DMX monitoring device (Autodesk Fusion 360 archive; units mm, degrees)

design "DMX monitoring device" references "rubber foot", "3D File NC5MAH", "longLCD_ESP32", "longLCD", "post", "nac3mpxxa", "3-D NC5FAH", "5V2AACDC", "conect"
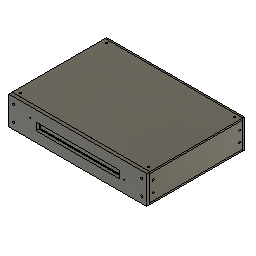
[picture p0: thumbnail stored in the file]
sketch "Sketch1" plane through (0, 0, 0) normal (0, 0, 1) x axis (1, 0, 0)
  line L1 (211.3, 0) -> (0, 0)
  line L2 (211.3, 150) -> (211.3, 0)
  line L3 (0, 150) -> (211.3, 150)
  line L4 (0, 0) -> (0, 150)
  point P1 (0, 0)
  point P2 (0, 0)
  point P3 (211.3, 0)
  point P5 (0, 150)
  horizontal L1
  vertical L2
  horizontal L3
  vertical L4
  coincident P1 P2
  dimension "d1" distance P2 P3 = 211.3
  dimension "d2" distance P2 P5 = 150
extrude "Extrude1" new body sketch "Sketch1" along normal blind 43.7
component_insert "Component Insert1"
component_insert "Component Insert2"
component_insert "Component Insert3"
component_insert "Component Insert4"
component_insert "Component Insert5"
component_insert "Component Insert6"
component_insert "Component Insert7"
component_insert "Component Insert8"
shell "Shell1" innerThickness 2.5
position "Position1" sketch "Sketch5"
sketch "Sketch2" plane through (0, 0, 0) normal (0, 0, 1) x axis (1, 0, 0)
  line L1 (211.3, 0) -> (0, 0)
  line L2 (211.3, 5) -> (211.3, 0)
  line L3 (0, 5) -> (211.3, 5)
  line L4 (0, 0) -> (0, 5)
  point P1 (0, 0)
  point P2 (0, 0)
  point P6 (211.3, 0)
  point P5 (0, 5)
  horizontal L1
  vertical L2
  horizontal L3
  vertical L4
  coincident P1 P2
  coincident L2 P6
  dimension "d6" distance P2 P5 = 5
extrude "Extrude1" new body sketch "Sketch2" to an object
sketch "Sketch4" plane through (0, 0, 0) normal (0, 0, 1) x axis (1, 0, 0)
  line L1 (211.3, 150) -> (0, 150)
  line L2 (211.3, 147.5) -> (211.3, 150)
  line L3 (0, 147.5) -> (211.3, 147.5)
  line L4 (0, 150) -> (0, 147.5)
  point P6 (211.3, 150)
  point P7 (0, 150)
  point P2 (0, 150)
  point P5 (0, 147.5)
  horizontal L1
  vertical L2
  horizontal L3
  vertical L4
  coincident L2 P6
  coincident L4 P7
  dimension "d9" distance P2 P5 = 2.5
extrude "Extrude1" new body sketch "Sketch4" to an object
sketch "Sketch5" plane through (0, 0, 0) normal (1, 0, 0) x axis (0, 1, 0)
  line L1 (147.5, 0) -> (5, 0)
  line L2 (147.5, 2.5) -> (147.5, 0)
  line L3 (5, 2.5) -> (147.5, 2.5)
  line L4 (5, 0) -> (5, 2.5)
  line L5 (5, 43.7) -> (5, 0)
  line L6 (147.5, 43.7) -> (5, 43.7)
  line L7 (147.5, 41.2) -> (147.5, 43.7)
  line L8 (5, 41.2) -> (147.5, 41.2)
  line L9 (5, 43.7) -> (5, 41.2)
  point P2 (5, 0)
  point P8 (147.5, 0)
  point P7 (5, 43.7)
  point P9 (5, 43.7)
  point P13 (147.5, 43.7)
  horizontal L1
  vertical L2
  horizontal L3
  vertical L4
  coincident P2 L5
  coincident L2 P8
  horizontal L6
  vertical L7
  horizontal L8
  vertical L9
  coincident P7 P9
  coincident L7 P13
  dimension "d12" distance L1 L3 = 2.5
  dimension "d13" distance L6 L8 = 2.5
extrude "Extrude1" new body sketch "Sketch5" profile of L1 L2 L3 L4 L5 to an object
extrude "Extrude1" new body sketch "Sketch5" profile of L5 L6 L7 L8 L9 to an object
sketch "Sketch6" plane through (0, 0, 2.5) normal (0, 0, 1) x axis (-1, 0, 0)
  line L1 (-211.3, -147.5) -> (-211.3, -5)
  line L2 (0, -147.5) -> (-211.3, -147.5)
  line L3 (0, -5) -> (0, -147.5)
  line L4 (-211.3, -5) -> (0, -5)
  line L5 (-2.5, -147.5) -> (0, -147.5)
  line L6 (-2.5, -5) -> (-2.5, -147.5)
  line L7 (0, -5) -> (-2.5, -5)
  line L8 (0, -147.5) -> (0, -5)
  point P4 (0, -147.5)
  point P6 (0, -147.5)
  point P7 (-2.5, -147.5)
  horizontal L5
  vertical L6
  horizontal L7
  vertical L8
  coincident P4 P6
  dimension "d18" distance P6 P7 = 2.5
extrude "Extrude1" new body sketch "Sketch6" profile of L2 L3 L4 L5 L6 L7 L8 to an object
sketch "Sketch7" plane through (0, 0, 2.5) normal (0, 0, 1) x axis (-1, 0, 0)
  line L1 (-211.3, -147.5) -> (-211.3, -5)
  line L2 (0, -147.5) -> (-211.3, -147.5)
  line L3 (0, -5) -> (0, -147.5)
  line L4 (-211.3, -5) -> (0, -5)
  line L5 (-208.8, -147.5) -> (-211.3, -147.5)
  line L6 (-208.8, -5) -> (-208.8, -147.5)
  line L7 (-211.3, -5) -> (-208.8, -5)
  line L8 (-211.3, -147.5) -> (-211.3, -5)
  point P3 (-211.3, -147.5)
  point P6 (-211.3, -147.5)
  point P2 (-211.3, -5)
  point P7 (-208.8, -147.5)
  horizontal L5
  vertical L6
  horizontal L7
  vertical L8
  coincident P3 P6
  coincident P2 L7
  dimension "d21" distance P6 P7 = 2.5
extrude "Extrude1" new body sketch "Sketch7" profile of L1 L2 L4 L5 L6 L7 L8 to an object
sketch "Sketch8" plane through (0, 150, 0) normal (0, 1, 0) x axis (-1, 0, 0)
  line L1 (-211.3, 43.7) -> (0, 43.7)
  line L2 (-211.3, 0) -> (-211.3, 43.7)
  line L3 (0, 0) -> (-211.3, 0)
  line L4 (0, 43.7) -> (0, 0)
  line L5 (0, 21.85) -> (-211.3, 21.85)
  line L6 (-105.65, 0) -> (-105.65, 43.7)
  line L7 (0, 38.3989) -> (-105.65, 38.3989)
  line L8 (-52.825, 0) -> (-52.825, 43.7)
  line L9 (-211.3, 38.3989) -> (-105.65, 38.3989)
  line L10 (-158.475, 43.7) -> (-158.475, 38.3989)
  line L11 (-158.475, 0) -> (-158.475, 38.3989)
  line L12 (-97.8724, 29.6288) -> (-105.65, 21.85)
  line L13 (-150.6965, 29.6279) -> (-158.475, 21.85)
  line L14 (-44.335, 30.3306) -> (-52.825, 21.85)
  circle C1 centre (-105.65, 21.85) radius 11
  circle C2 centre (-158.475, 21.85) radius 11
  circle C3 centre (-52.825, 21.85) radius 12
  circle C4 centre (-43.325, 9.85) radius 1.5
  circle C5 centre (-95.75, 11.95) radius 1.5
  circle C6 centre (-148.575, 11.95) radius 1.5
  circle C7 centre (-115.5516, 31.7484) radius 1.5
  circle C8 centre (-168.3742, 31.7508) radius 1.5
  circle C9 centre (-62.325, 33.85) radius 1.5
  point P6 (-211.3, 21.85)
  point P7 (0, 21.85)
  point P8 (-105.65, 43.7)
  point P9 (-105.65, 0)
  point P10 (-105.65, 21.85)
  point P11 (-105.65, 38.3989)
  point P12 (0, 38.3989)
  point P13 (-52.825, 43.7)
  point P14 (-52.825, 0)
  point P15 (-211.3, 38.3989)
  point P16 (-158.475, 38.3989)
  point P17 (-158.475, 43.7)
  point P18 (-158.475, 0)
  point P19 (-158.475, 21.85)
  point P20 (-52.825, 21.85)
  point P24 (-105.65, 21.85)
  point P25 (-97.8724, 29.6288)
  point P27 (-158.475, 21.85)
  point P28 (-150.6965, 29.6279)
  point P30 (-52.825, 38.3989)
  point P31 (-52.825, 21.85)
  point P32 (-44.335, 30.3306)
  point P22 (-95.75, 11.95)
  point P23 (-148.575, 11.95)
  point P21 (-43.325, 9.85)
  point P33 (-62.325, 33.85)
  midpoint L2 P6
  midpoint L4 P7
  midpoint L1 P8
  midpoint L3 P9
  midpoint L5 P10
  coincident L6 P11
  coincident L4 P12
  perpendicular L4 L7
  coincident L1 P13
  coincident L3 P14
  perpendicular L3 L8
  coincident L2 P15
  perpendicular L2 L9
  midpoint L9 P16
  coincident L1 P17
  perpendicular L1 L10
  coincident L3 P18
  perpendicular L3 L11
  coincident L5 P19
  coincident L11 P19
  midpoint L8 P20
  coincident P10 P24
  coincident C1 P25
  symmetric C5 L12 C7
  coincident P19 P27
  coincident C2 P28
  symmetric C6 L13 C8
  midpoint L7 P30
  coincident L8 P30
  coincident P20 P31
  coincident C3 P32
  dimension "d24" diameter C1 = 22
  dimension "d25" diameter C2 = 22
  dimension "d26" diameter C3 = 24
  dimension "d27" diameter C4 = 3
  dimension "d28" diameter C5 = 3
  dimension "d29" diameter C6 = 3
  dimension "d31" distance L5 P22 = 9.9
  dimension "d32" distance L6 P22 = 9.9
  dimension "d33" distance L5 P23 = 9.9
  dimension "d34" distance L11 P23 = 9.9
  dimension "d35" distance L5 P21 = 12
  dimension "d36" distance L8 P21 = 9.5
  dimension "d37" diameter C9 = 3
  dimension "d38" distance L8 P33 = 9.5
  dimension "d39" distance L5 P33 = 12
extrude "Extrude2" cut sketch "Sketch8" profile of L5 L6 C1 L8 L11 C2 C3 C4 C5 C6 L12 C7 C8 C9 against normal blind 10
step "GeometricRelationship1" Offset 0
step "GeometricRelationship2" Offset 0
step "GeometricRelationship3" sketch "Sketch5" Offset 0
component_insert "Component Insert9"
component_insert "Component Insert10"
component_insert "Component Insert11"
component_insert "Component Insert12"
position "Position2"
sketch "Sketch9" plane through (0, 0, 0) normal (0, 0, -1) x axis (1, 0, 0)
  line L1 (211.3, -5) -> (211.3, -147.5)
  line L2 (0, -5) -> (211.3, -5)
  line L3 (0, -147.5) -> (0, -5)
  line L4 (211.3, -147.5) -> (0, -147.5)
  line L5 (211.3, 0) -> (0, 0)
  line L6 (211.3, -150) -> (0, -150)
  circle C1 centre (30, -30) radius 2.5
  circle C2 centre (20, -20) radius 15
  circle C3 centre (181.3, -30) radius 2.5
  circle C4 centre (191.3, -20) radius 15
  circle C5 centre (181.3, -120) radius 2.5
  circle C6 centre (191.3, -130) radius 15
  circle C7 centre (30, -120) radius 2.5
  circle C8 centre (20, -130) radius 15
  point P6 (30, -30)
  point P8 (181.3, -30)
  point P10 (181.3, -120)
  point P12 (30, -120)
  dimension "d45" diameter C1 = 5
  dimension "d46" diameter C3 = 5
  dimension "d47" diameter C5 = 5
  dimension "d48" diameter C7 = 5
  dimension "d51" distance P6 L5 = 30
  dimension "d52" distance L3 P6 = 30
  dimension "d53" distance P8 L5 = 30
  dimension "d54" distance L1 P8 = 30
  dimension "d55" distance L1 P10 = 30
  dimension "d56" distance P10 L6 = 30
  dimension "d57" distance P12 L6 = 30
  dimension "d58" distance L3 P12 = 30
extrude "Extrude2" cut sketch "Sketch9" profile of C1 C3 C5 C7 against normal blind 10
sketch "Sketch10" plane through (0, 0, 0) normal (0, -1, 0) x axis (1, 0, 0)
  line L1 (0, 43.7) -> (211.3, 43.7)
  line L2 (0, 0) -> (0, 43.7)
  line L3 (211.3, 0) -> (0, 0)
  line L4 (211.3, 43.7) -> (211.3, 0)
  line L5 (211.3, 21.85) -> (0, 21.85)
  line L6 (105.65, 0) -> (105.65, 43.7)
  point P6 (0, 21.85)
  point P7 (211.3, 21.85)
  point P8 (105.65, 43.7)
  point P9 (105.65, 0)
  midpoint L2 P6
  midpoint L4 P7
  midpoint L1 P8
  midpoint L3 P9
position "Position3"
extrude "Extrude2" cut blind 60
position "Position4"
sketch "Sketch11" plane through (0, 0.009, 0) normal (0, -1, 0) x axis (1, 0, 0)
  line L1 (-0.0961, 43.8699) -> (211.2039, 43.8699)
  line L2 (-0.0961, 0.1699) -> (-0.0961, 43.8699)
  line L3 (211.2039, 0.1699) -> (-0.0961, 0.1699)
  line L4 (211.2039, 43.8699) -> (211.2039, 0.1699)
  line L5 (41.65, 27.6) -> (169.65, 27.6)
  line L6 (41.65, 16.1) -> (41.65, 27.6)
  line L7 (169.65, 16.1) -> (41.65, 16.1)
  line L8 (169.65, 27.6) -> (169.65, 16.1)
  line L9 (41.65, 16.1) -> (169.65, 27.6)
  line L10 (169.65, 16.1) -> (41.65, 27.6)
  line L11 (105.65, 17.1) -> (105.65, 26.6)
  line L12 (168.65, 21.85) -> (42.65, 21.85)
  line L13 (168.65, 17.1) -> (168.65, 26.6)
  line L14 (168.65, 26.6) -> (42.65, 26.6)
  circle C1 centre (176.9039, 18.4199) radius 1.05
  circle C2 centre (32.9039, 28.6199) radius 1.05
  point P12 (105.65, 21.85)
  horizontal L5
  perpendicular L5 L6
  parallel L5 L7
  parallel L6 L8
  coincident L9 P12
  coincident L10 P12
  coincident P12 L11
  coincident P12 L12
  dimension "d63" distance L8 L13 = 1
  dimension "d64" distance L5 L14 = 1
extrude "Extrude4" cut sketch "Sketch11" profile of L5 L6 L7 L8 L11 L12 L13 L14 against normal blind 5
step "GeometricRelationship4" sketch "Sketch5" Offset 0
step "GeometricRelationship5" sketch "Sketch5" Offset 0
step "GeometricRelationship6" sketch "Sketch5" Offset 0
step "GeometricRelationship7" sketch "Sketch5" Offset 0
position "Position5"
position "Position6"
component_insert "Component Insert13"
component_insert "Component Insert14"
component_insert "Component Insert15"
component_insert "Component Insert16"
sketch "スケッチ14" plane through (0, 0, 43.7) normal (0, 0, 1) x axis (-1, 0, 0)
  line L1 (-211.3, -147.5) -> (-211.3, -5)
  line L2 (0, -147.5) -> (-211.3, -147.5)
  line L3 (0, -5) -> (0, -147.5)
  line L4 (-211.3, -5) -> (0, -5)
  circle C1 centre (-7.5, -10) radius 1.5
  circle C2 centre (-7.5, -142.5) radius 1.5
  circle C3 centre (-203.8, -142.5) radius 1.5
  circle C4 centre (-203.8, -10) radius 1.5
  dimension "d77" diameter C1 = 3
  dimension "d78" diameter C2 = 3
  dimension "d79" diameter C3 = 3
  dimension "d80" diameter C4 = 3
extrude "押し出し2" cut sketch "スケッチ14" profile of C1 C2 C3 C4 distance -90
sketch "スケッチ15" plane through (0, 0.009, 0) normal (0, -1, 0) x axis (1, 0, 0)
  line L1 (169.65, 27.4031) -> (41.65, 27.4031)
  line L2 (169.65, 15.9031) -> (169.65, 27.4031)
  line L3 (41.65, 15.9031) -> (169.65, 15.9031)
  line L4 (41.65, 27.4031) -> (41.65, 15.9031)
  line L5 (-0.0961, 43.6729) -> (211.2039, 43.6729)
  line L6 (-0.0961, -0.0271) -> (-0.0961, 43.6729)
  line L7 (211.2039, -0.0271) -> (-0.0961, -0.0271)
  line L8 (211.2039, 43.6729) -> (211.2039, -0.0271)
  line L9 (169.65, 27.4031) -> (41.65, 27.4031)
  line L10 (169.65, 15.9031) -> (169.65, 27.4031)
  line L11 (41.65, 15.9031) -> (169.65, 15.9031)
  line L12 (41.65, 27.4031) -> (41.65, 15.9031)
  line L13 (-0.0961, 43.6729) -> (211.2039, 43.6729)
  line L14 (-0.0961, -0.0271) -> (-0.0961, 43.6729)
  line L15 (211.2039, -0.0271) -> (-0.0961, -0.0271)
  line L16 (211.2039, 43.6729) -> (211.2039, -0.0271)
  circle C1 centre (176.9039, 18.2229) radius 1.05
  circle C2 centre (32.9039, 28.4229) radius 1.05
  circle C3 centre (7.5, 33.7) radius 1.5
  circle C4 centre (203.8, 33.7) radius 1.5
  circle C5 centre (203.8, 10) radius 1.5
  circle C6 centre (176.9039, 18.2229) radius 1.05
  circle C7 centre (32.9039, 28.4229) radius 1.05
  circle C8 centre (7.5, 10) radius 1.5
  dimension "d85" diameter C3 = 3
  dimension "d87" diameter C4 = 3
  dimension "d88" diameter C5 = 3
extrude "押し出し5" cut sketch "スケッチ15" profile of C3 C4 C5 C8 against normal blind 190
sketch "スケッチ16" plane through (211.3, 0, 0) normal (1, 0, 0) x axis (0, 1, 0)
  line L1 (5, 41.2) -> (147.5, 41.2)
  line L2 (5, 2.5) -> (5, 41.2)
  line L3 (147.5, 2.5) -> (5, 2.5)
  line L4 (147.5, 41.2) -> (147.5, 2.5)
  circle C1 centre (10, 30.2) radius 1.5
  circle C2 centre (10, 13.5) radius 1.5
  circle C3 centre (142.5, 13.5) radius 1.5
  circle C4 centre (142.5, 30.2) radius 1.5
extrude "押し出し2" cut sketch "スケッチ16" profile of C1 C2 C3 C4 against normal blind 230
position "位置"
hole "穴1" HoleDepth 40 HoleDiameter 3 TipAngle 180
hole "穴2" HoleDepth 40 HoleDiameter 3 TipAngle 180
hole "穴3" HoleDepth 40 HoleDiameter 3 TipAngle 180
hole "穴4" HoleDepth 40 HoleDiameter 3 TipAngle 180
sketch "スケッチ17" plane through (0, 0, 0) normal (0, 0, -1) x axis (1, 0, 0)
  line L1 (211.3, -5) -> (211.3, -147.5)
  line L2 (0, -5) -> (211.3, -5)
  line L3 (0, -147.5) -> (0, -5)
  line L4 (211.3, -147.5) -> (0, -147.5)
  circle C1 centre (30, -120) radius 2.5
  circle C2 centre (30, -30) radius 2.5
  circle C3 centre (181.3, -120) radius 2.5
  circle C4 centre (181.3, -30) radius 2.5
  circle C5 centre (185.92, -49.28) radius 1.5
  circle C6 centre (189.73, -101.604) radius 1.5
  circle C7 centre (162.552, -101.604) radius 1.5
  circle C8 centre (198.62, -49.28) radius 1.5
  circle C9 centre (7.5, -10) radius 1.5
  circle C10 centre (203.8, -10) radius 1.5
  circle C11 centre (7.5, -142.5) radius 1.5
  circle C12 centre (203.8, -142.5) radius 1.5
  dimension "d111" diameter C12 = 3
extrude "押し出し6" cut sketch "スケッチ17" profile of C9 C10 C11 C12 against normal blind 70
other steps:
extrude "押し出し2" cut sketch "スケッチ16" profile of C1 C2 C3 C4 against normal blind 230
extrude "押し出し3" cut sketch "スケッチ15" profile of C3 C4 C5 C8 against normal blind 190
create_component "CreateComponent1"
create_component "CreateComponent2"
create_component "CreateComponent3"
create_component "CreateComponent4"
create_component "CreateComponent5"
create_component "CreateComponent6"

design "post"
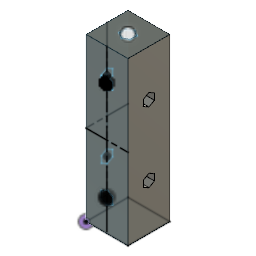
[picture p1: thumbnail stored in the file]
sketch "Sketch1" plane through (0, 0, 0) normal (0, 0, 1) x axis (1, 0, 0)
  line L1 (10, 0) -> (0, 0)
  line L2 (10, 10) -> (10, 0)
  line L3 (0, 10) -> (10, 10)
  line L4 (0, 0) -> (0, 10)
  point P1 (0, 0)
  point P2 (0, 0)
  point P3 (10, 0)
  point P5 (0, 10)
  horizontal L1
  vertical L2
  horizontal L3
  vertical L4
  coincident P1 P2
  dimension "d1" distance P2 P3 = 10
  dimension "d2" distance P2 P5 = 10
extrude "Extrude1" new body sketch "Sketch1" along normal blind 38.7
sketch "Sketch2" plane through (0, 0, 38.7) normal (0, 0, 1) x axis (-1, 0, 0)
  line L1 (0, 0) -> (0, -10)
  line L2 (-10, 0) -> (0, 0)
  line L3 (-10, -10) -> (-10, 0)
  line L4 (0, -10) -> (-10, -10)
  line L5 (-4.9676, -3.4992) -> (-3.6841, -4.2777)
  line L6 (-6.2835, -4.2216) -> (-4.9676, -3.4992)
  line L7 (-6.3159, -5.7223) -> (-6.2835, -4.2216)
  line L8 (-5.0324, -6.5008) -> (-6.3159, -5.7223)
  line L9 (-3.7165, -5.7784) -> (-5.0324, -6.5008)
  line L10 (-3.6841, -4.2777) -> (-3.7165, -5.7784)
  point P12 (-5, -5)
  dimension "d5" distance P12 L10 = 1.3
extrude "Extrude2" cut sketch "Sketch2" profile of L5 L6 L7 L8 L9 L10 against normal blind 48
sketch "Sketch3" plane through (0, 0, 0) normal (0, -1, 0) x axis (1, 0, 0)
  line L1 (10, 0) -> (0, 0)
  line L2 (10, 38.7) -> (10, 0)
  line L3 (0, 38.7) -> (10, 38.7)
  line L4 (0, 0) -> (0, 38.7)
  line L5 (5, 0) -> (5, 38.7)
  line L6 (10, 19.35) -> (0, 19.35)
  line L7 (5, 32.7011) -> (6.3, 31.9506)
  line L8 (3.7, 31.9506) -> (5, 32.7011)
  line L9 (3.7, 30.4494) -> (3.7, 31.9506)
  line L10 (5, 29.6989) -> (3.7, 30.4494)
  line L11 (6.3, 30.4494) -> (5, 29.6989)
  line L12 (6.3, 31.9506) -> (6.3, 30.4494)
  line L13 (3.7, 8.2506) -> (3.7, 6.7494)
  line L14 (6.3, 8.2506) -> (5, 9.0011)
  line L15 (5, 5.9989) -> (6.3, 6.7494)
  line L16 (6.3, 6.7494) -> (6.3, 8.2506)
  line L17 (5, 9.0011) -> (3.7, 8.2506)
  line L18 (3.7, 6.7494) -> (5, 5.9989)
  point P6 (5, 38.7)
  point P7 (5, 0)
  point P8 (5, 31.2)
  point P9 (0, 19.35)
  point P10 (10, 19.35)
  point P17 (5, 31.2)
  point P19 (5, 7.5)
  point P11 (6.3, 31.9506)
  point P18 (6.3, 6.7494)
  point P12 (5, 32.7011)
  point P22 (5, 5.9989)
  point P13 (3.7, 31.9506)
  point P25 (3.7, 6.7494)
  point P14 (3.7, 30.4494)
  point P24 (3.7, 8.2506)
  point P15 (5, 29.6989)
  point P21 (5, 9.0011)
  point P16 (6.3, 30.4494)
  point P20 (6.3, 8.2506)
  point P23 (5, 7.5)
  midpoint L3 P6
  midpoint L1 P7
  coincident L5 P8
  midpoint L4 P9
  midpoint L2 P10
  coincident P8 P17
  symmetric P8 L6 P19
  symmetric L6 P11 P18
  symmetric L6 P12 P22
  symmetric L6 P13 P25
  symmetric L6 P14 P24
  symmetric L6 P15 P21
  symmetric L6 P16 P20
  symmetric L6 P17 P23
  dimension "d8" distance L3 P8 = 7.5
  dimension "d9" distance P17 L12 = 1.3
extrude "Extrude3" cut sketch "Sketch3" profile of L5 L7 L8 L9 L10 L11 L12 L13 L14 L15 L16 L17 L18 against normal blind 23
sketch "Sketch4" plane through (0, 0, 0) normal (-1, 0, 0) x axis (0, -1, 0)
  line L1 (0, 0) -> (-10, 0)
  line L2 (0, 38.7) -> (0, 0)
  line L3 (-10, 38.7) -> (0, 38.7)
  line L4 (-10, 0) -> (-10, 38.7)
  line L5 (-5, 0) -> (-5, 38.7)
  line L6 (0, 19.35) -> (-10, 19.35)
  line L7 (-4.9908, 26.1989) -> (-6.2954, 26.9415)
  line L8 (-3.6954, 26.9574) -> (-4.9908, 26.1989)
  line L9 (-3.7046, 28.4585) -> (-3.6954, 26.9574)
  line L10 (-5.0092, 29.2011) -> (-3.7046, 28.4585)
  line L11 (-6.3046, 28.4426) -> (-5.0092, 29.2011)
  line L12 (-6.2954, 26.9415) -> (-6.3046, 28.4426)
  line L13 (-5.0092, 9.4989) -> (-3.7046, 10.2415)
  line L14 (-6.3046, 10.2574) -> (-5.0092, 9.4989)
  line L15 (-6.2954, 11.7585) -> (-6.3046, 10.2574)
  line L16 (-3.7046, 10.2415) -> (-3.6954, 11.7426)
  line L17 (-3.6954, 11.7426) -> (-4.9908, 12.5011)
  line L18 (-4.9908, 12.5011) -> (-6.2954, 11.7585)
  point P6 (-5, 38.7)
  point P7 (-5, 0)
  point P8 (-10, 19.35)
  point P9 (0, 19.35)
  point P10 (-5, 27.7)
  point P17 (-5, 27.7)
  point P20 (-5, 11)
  point P11 (-6.2954, 26.9415)
  point P19 (-6.2954, 11.7585)
  point P12 (-4.9908, 26.1989)
  point P23 (-4.9908, 12.5011)
  point P13 (-3.6954, 26.9574)
  point P24 (-3.6954, 11.7426)
  point P14 (-3.7046, 28.4585)
  point P22 (-3.7046, 10.2415)
  point P15 (-5.0092, 29.2011)
  point P21 (-5.0092, 9.4989)
  point P16 (-6.3046, 28.4426)
  point P18 (-6.3046, 10.2574)
  point P25 (-5, 11)
  midpoint L3 P6
  midpoint L1 P7
  midpoint L4 P8
  midpoint L2 P9
  coincident L5 P10
  coincident P10 P17
  symmetric L6 P10 P20
  symmetric L6 P11 P19
  symmetric L6 P12 P23
  symmetric L6 P13 P24
  symmetric L6 P14 P22
  symmetric L6 P15 P21
  symmetric L6 P16 P18
  symmetric L6 P17 P25
  dimension "d12" distance P6 P10 = 11
  dimension "d13" distance P17 L12 = 1.3
extrude "Extrude4" cut sketch "Sketch4" profile of L5 L7 L8 L9 L10 L11 L12 L13 L14 L15 L16 L17 L18 against normal blind 19

design "5V2AACDC"
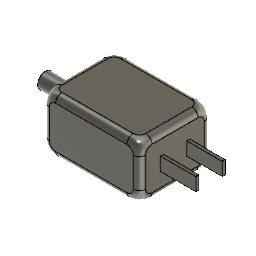
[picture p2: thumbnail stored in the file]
sketch "Sketch1" plane through (0, 0, 0) normal (0, 0, 1) x axis (1, 0, 0)
  line L1 (-23, 17) -> (23, 17)
  line L2 (-23, -17) -> (-23, 17)
  line L3 (23, -17) -> (-23, -17)
  line L4 (23, 17) -> (23, -17)
  line L5 (-23, -17) -> (23, 17)
  line L6 (23, -17) -> (-23, 17)
  point P6 (0, 0)
  point P1 (0, 0)
  point P4 (-23, -17)
  point P5 (23, -17)
  point P3 (-23, 17)
  horizontal L1
  perpendicular L1 L2
  parallel L1 L3
  parallel L2 L4
  coincident L5 P6
  coincident L6 P6
  coincident P1 P6
  dimension "d3" distance P4 P5 = 46
  dimension "d4" distance P3 P4 = 34
extrude "Extrude1" new body sketch "Sketch1" profile of L1 L2 L3 L4 along normal blind 26
sketch "Sketch2" plane through (-23, 0, 0) normal (-1, 0, 0) x axis (0, -1, 0)
  line L1 (17, 0) -> (-17, 0)
  line L2 (17, 26) -> (17, 0)
  line L3 (-17, 26) -> (17, 26)
  line L4 (-17, 0) -> (-17, 26)
  circle C1 centre (0, 13) radius 3.75
  dimension "d5" diameter C1 = 7.5
extrude "Extrude2" add sketch "Sketch2" profile of C1 along normal blind 16
sketch "Sketch3" plane through (23, 0, 0) normal (1, 0, 0) x axis (0, 1, 0)
  line L1 (17, 0) -> (-17, 0)
  line L2 (17, 26) -> (17, 0)
  line L3 (-17, 26) -> (17, 26)
  line L4 (-17, 0) -> (-17, 26)
  line L5 (-7.05, 16.175) -> (7.05, 16.175)
  line L6 (-7.05, 9.825) -> (-7.05, 16.175)
  line L7 (7.05, 9.825) -> (-7.05, 9.825)
  line L8 (7.05, 16.175) -> (7.05, 9.825)
  line L9 (-7.05, 9.825) -> (7.05, 16.175)
  line L10 (7.05, 9.825) -> (-7.05, 16.175)
  line L11 (-5.55, 16.175) -> (-7.05, 16.175)
  line L12 (-5.55, 9.825) -> (-5.55, 16.175)
  line L13 (-7.05, 9.825) -> (-5.55, 9.825)
  line L14 (-7.05, 16.175) -> (-7.05, 9.825)
  line L15 (5.55, 16.175) -> (7.05, 16.175)
  line L16 (5.55, 9.825) -> (5.55, 16.175)
  line L17 (7.05, 9.825) -> (5.55, 9.825)
  line L18 (7.05, 16.175) -> (7.05, 9.825)
  point P10 (0, 13)
  point P8 (-7.05, 9.825)
  point P9 (7.05, 9.825)
  point P7 (-7.05, 16.175)
  point P11 (-5.55, 16.175)
  point P6 (7.05, 16.175)
  point P14 (5.55, 16.175)
  horizontal L5
  perpendicular L5 L6
  parallel L5 L7
  parallel L6 L8
  coincident L9 P10
  coincident L10 P10
  horizontal L11
  vertical L12
  horizontal L13
  vertical L14
  horizontal L15
  vertical L16
  horizontal L17
  vertical L18
  dimension "d8" distance P8 P9 = 14.1
  dimension "d9" distance P7 P8 = 6.35
  dimension "d10" distance P7 P11 = 1.5
  dimension "d11" distance P6 P14 = 1.5
extrude "Extrude3" add sketch "Sketch3" profile of L11 L12 L13 L14 L15 L16 L17 L18 along normal blind 17
fillet "Fillet1" radius 3

design "longLCD_ESP32"
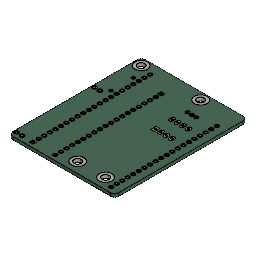
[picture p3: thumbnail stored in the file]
description: KiCad electronic assembly
part number: longLCD_ESP32 1
description: Part Number
part number: DIP-8_W7.62mm_Socket
part number: longLCD_ESP32_copper
part number: longLCD_ESP32_pad
part number: longLCD_ESP32_PCB
part number: PinHeader_1x22_P2.54mm_Vertical
base_feature "Base Feature1"
base_feature "Base Feature1"
base_feature "Base Feature1"
base_feature "Base Feature1"
base_feature "Base Feature1"
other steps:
create_component "CreateComponent1"
create_component "CreateComponent2"
create_component "CreateComponent3"
create_component "CreateComponent4"
create_component "CreateComponent5"

design "3-D NC5FAH"
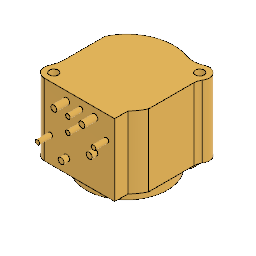
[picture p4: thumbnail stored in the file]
description: Part Number
part number: D-NC5FAH
base_feature "Base Feature"

design "conect"
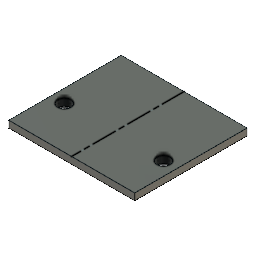
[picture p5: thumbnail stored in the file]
sketch "Sketch1" plane through (0, 0, 0) normal (0, 0, 1) x axis (1, 0, 0)
  line L1 (29.1, 0) -> (0, 0)
  line L2 (29.1, 26) -> (29.1, 0)
  line L3 (0, 26) -> (29.1, 26)
  line L4 (0, 0) -> (0, 26)
  point P1 (0, 0)
  point P2 (0, 0)
  point P3 (29.1, 0)
  point P5 (0, 26)
  horizontal L1
  vertical L2
  horizontal L3
  vertical L4
  coincident P1 P2
  dimension "d1" distance P2 P3 = 29.1
  dimension "d2" distance P2 P5 = 26
extrude "Extrude1" new body sketch "Sketch1" along normal blind 1.6
sketch "Sketch2" plane through (0, 0, 1.6) normal (0, 0, 1) x axis (-1, 0, 0)
  line L1 (0, 0) -> (0, -26)
  line L2 (-29.1, 0) -> (0, 0)
  line L3 (-29.1, -26) -> (-29.1, 0)
  line L4 (0, -26) -> (-29.1, -26)
  line L5 (-14.55, 0) -> (-14.55, -26)
  circle C1 centre (-26, -9.75) radius 1.5
  circle C2 centre (-3.1, -9.75) radius 1.5
  point P6 (-14.55, -26)
  point P7 (-14.55, 0)
  point P8 (-26, -9.75)
  midpoint L4 P6
  midpoint L2 P7
  symmetric L5 C1 C2
  dimension "d5" diameter C1 = 3
  dimension "d6" distance L3 P8 = 3.1
  dimension "d7" distance L2 P8 = 9.75
extrude "Extrude2" cut sketch "Sketch2" profile of C1 C2 against normal blind 4

design "longLCD"
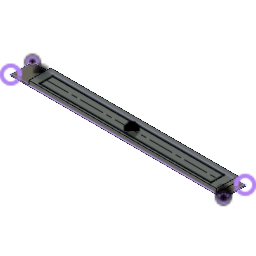
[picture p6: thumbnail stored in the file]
sketch "Sketch1" plane through (0, 0, 0) normal (0, 0, 1) x axis (1, 0, 0)
  line L1 (156.5, 0) -> (0, 0)
  line L2 (156.5, 16) -> (156.5, 0)
  line L3 (0, 16) -> (156.5, 16)
  line L4 (0, 0) -> (0, 16)
  point P1 (0, 0)
  point P2 (0, 0)
  point P3 (156.5, 0)
  point P5 (0, 16)
  horizontal L1
  vertical L2
  horizontal L3
  vertical L4
  coincident P1 P2
  dimension "d1" distance P2 P3 = 156.5
  dimension "d2" distance P2 P5 = 16
extrude "Extrude1" new body sketch "Sketch1" along normal blind 0.9
sketch "Sketch2" plane through (0, 0, 0.9) normal (0, 0, 1) x axis (-1, 0, 0)
  line L1 (0, 0) -> (0, -16)
  line L2 (-156.5, 0) -> (0, 0)
  line L3 (-156.5, -16) -> (-156.5, 0)
  line L4 (0, -16) -> (-156.5, -16)
  line L5 (-13.5, 0) -> (-151.5, 0)
  line L6 (-13.5, -16) -> (-13.5, 0)
  line L7 (-151.5, -16) -> (-13.5, -16)
  line L8 (-151.5, 0) -> (-151.5, -16)
  point P6 (-151.5, 0)
  point P7 (-151.5, 0)
  point P4 (-156.5, 0)
  point P8 (-13.5, 0)
  point P10 (-151.5, -16)
  coincident L2 P6
  horizontal L5
  vertical L6
  horizontal L7
  vertical L8
  coincident P6 P7
  dimension "d5" distance P4 P6 = 5
  dimension "d6" distance P7 P8 = 138
  dimension "d7" distance P7 P10 = 16
extrude "Extrude2" add sketch "Sketch2" profile of L2 L4 L5 L6 L7 L8 along normal blind 3.1
sketch "Sketch3" plane through (0, 0, 4) normal (0, 0, 1) x axis (-1, 0, 0)
  line L1 (-13.5, -16) -> (-151.5, -16)
  line L2 (-13.5, 0) -> (-13.5, -16)
  line L3 (-151.5, 0) -> (-13.5, 0)
  line L4 (-151.5, -16) -> (-151.5, 0)
  line L5 (-145.5, -11.3) -> (-19.5, -11.3)
  line L6 (-145.5, -1.8) -> (-145.5, -11.3)
  line L7 (-19.5, -1.8) -> (-145.5, -1.8)
  line L8 (-19.5, -11.3) -> (-19.5, -1.8)
  line L9 (-145.5, -6.55) -> (-19.5, -6.55)
  line L10 (-82.5, -1.8) -> (-82.5, -11.3)
  point P10 (-19.5, -6.55)
  point P11 (-145.5, -6.55)
  point P12 (-82.5, -11.3)
  point P13 (-82.5, -1.8)
  point P14 (-82.5, -6.55)
  horizontal L5
  vertical L6
  horizontal L7
  vertical L8
  midpoint L8 P10
  midpoint L6 P11
  midpoint L5 P12
  midpoint L7 P13
  midpoint L9 P14
  dimension "d10" distance L3 L7 = 1.8
  dimension "d11" distance L4 L6 = 6
  dimension "d12" distance L2 L8 = 6
  dimension "d13" distance L1 L5 = 4.7
extrude "Extrude3" cut sketch "Sketch3" profile of L5 L6 L7 L8 against normal blind 0.2
sketch "Sketch4" plane through (0, 0, 0.9) normal (0, 0, 1) x axis (-1, 0, 0)
  line L1 (-156.5, 0) -> (0, 0)
  line L2 (-156.5, -16) -> (-156.5, 0)
  circle C1 centre (-153.85, -2.95) radius 1.05
  point P2 (-153.85, -2.95)
  dimension "d16" diameter C1 = 2.1
  dimension "d17" distance P2 L1 = 2.95
  dimension "d18" distance P2 L2 = 2.65
sketch "Sketch5" plane through (0, 0, 0.9) normal (0, 0, 1) x axis (-1, 0, 0)
  line L1 (0, -16) -> (-156.5, -16)
  line L2 (0, 0) -> (0, -16)
  circle C1 centre (-9.85, -13.15) radius 1.05
  point P2 (-9.85, -13.15)
  dimension "d21" diameter C1 = 2.1
  dimension "d22" distance P2 L1 = 2.85
  dimension "d23" distance P2 L2 = 9.85
extrude "Extrude4" cut sketch "Sketch4" + "Sketch5" profile of S1:C1 S2:C1 blind -5

design "nac3mpxxa"
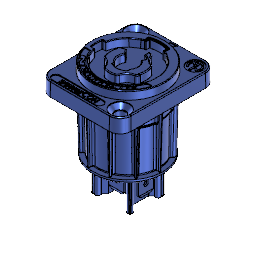
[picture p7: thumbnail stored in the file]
description: Part Number
part number: NAC3MPXXA
base_feature "Base Feature"

design "rubber foot"
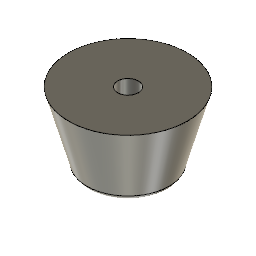
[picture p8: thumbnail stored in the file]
sketch "Sketch1" plane through (0, 0, 0) normal (0, 1, 0) x axis (1, 0, 0)
  line L1 (0, -18) -> (0, 0)
  line L2 (10, 0) -> (0, 0)
  line L3 (15, -18) -> (0, -18)
  line L4 (10, 0) -> (15, -18)
  point P1 (0, 0)
  point P2 (0, 0)
  point P3 (0, -18)
  point P4 (10, 0)
  point P5 (15, -18)
  coincident P1 P2
  vertical L1
  perpendicular L1 L2
  perpendicular L1 L3
  dimension "d1" distance P2 P3 = 18
  dimension "d2" distance P2 P4 = 10
  dimension "d3" distance P3 P5 = 15
revolve "Revolve1" sketch "Sketch1" AlongAngle 360
fillet "Fillet1" radius 2
sketch "Sketch2" plane through (0, 0, 0) normal (0, 0, -1) x axis (1, 0, 0)
  circle C1 centre (0, 0) radius 8.4798
  circle C2 centre (0, 0) radius 2.6
  concentric C1 C2
  dimension "d7" diameter C2 = 5.2
extrude "Extrude1" cut sketch "Sketch2" profile of C2 against normal blind 35
sketch "Sketch3" plane through (0, 0, 0) normal (0, 0, -1) x axis (1, 0, 0)
  circle C1 centre (0, 0) radius 2.6
  circle C2 centre (0, 0) radius 8.4798
  circle C3 centre (0, 0) radius 5.25
  point P1 (0, 0)
  point P3 (0, 0)
  coincident P1 P3
  dimension "d10" diameter C3 = 10.5
extrude "Extrude2" cut sketch "Sketch3" profile of C1 C3 against normal blind 8

design "3D File NC5MAH"
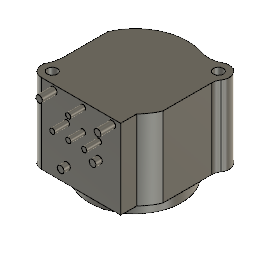
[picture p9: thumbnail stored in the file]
description: Part Number
part number: D-NC5MAH
base_feature "Base Feature"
